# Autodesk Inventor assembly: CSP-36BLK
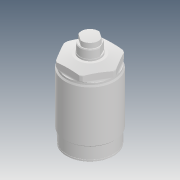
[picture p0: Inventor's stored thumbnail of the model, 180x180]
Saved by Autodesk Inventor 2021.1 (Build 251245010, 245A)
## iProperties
Created: 2019-01
Part Number: CSP-36BLK
Description: STEP AP203
Document SubType Name: Assembly
Designer: user
Title: CSP-036BLK.STEP
Revision Number: ÈÎºÎ
Sending System: SolidWorks 2014
Preprocessor: SwSTEP 2.0
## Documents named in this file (4)
- D:\Vault_2016\Projekty\Clamptek\Hydraulic\CSP-P-K\CSP-36KP\Inventor\CSP-36BLK\CSP-36BLK.iam
- D:\Vault_2016\Projekty\Clamptek\Hydraulic\CSP-P-K\CSP-36KP\Inventor\CSP-36BLK\CSP-036-K±¾Ìå£¨³õÊ¼£©.ipt
- D:\Vault_2016\Projekty\Clamptek\Hydraulic\CSP-P-K\CSP-36KP\Inventor\CSP-36BLK\CSP-036»îÈû¸Ë.ipt
- D:\Vault_2016\Projekty\Clamptek\Hydraulic\CSP-P-K\CSP-36KP\Inventor\CSP-36BLK\CSP-036Ô²Í·ÂÝË¨.ipt
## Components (3 placed, 3 different names)
1. CSP-036-K±¾Ìå£¨³õÊ¼£©_1
2. CSP-036»îÈû¸Ë_2
3. CSP-036Ô²Í·ÂÝË¨_3
